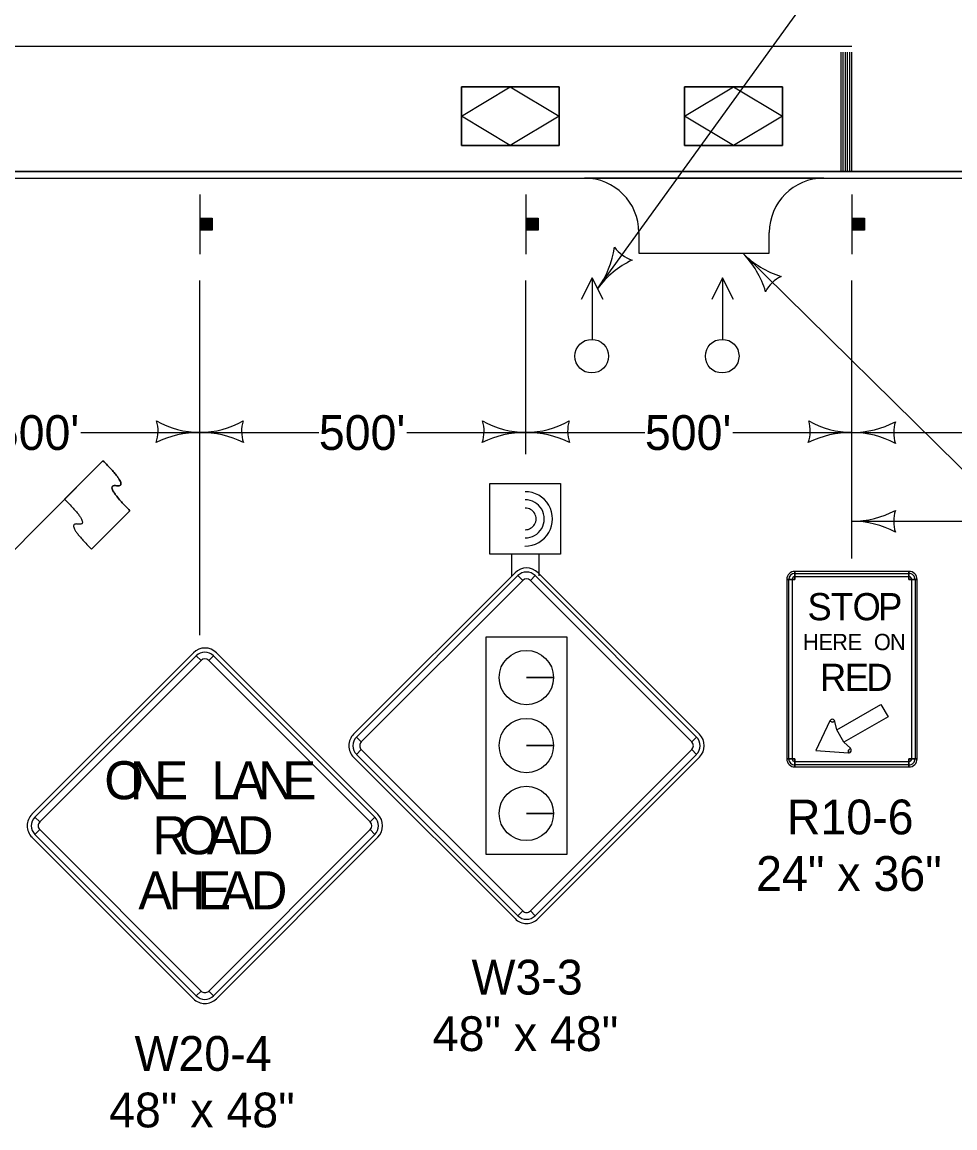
# Model space of a CAD drawing. Extents: x -2134934 to -2122394, y -2139046 to -2137036.
# Drawn here: x -2134616 to -2134187, y -2138105 to -2137596 of the extents above; entities that cross this region are included whole.
import ezdxf

# ---------------------------------------------------------------- set-up
doc = ezdxf.new("R2010")
doc.units = 0
for name, color, linetype in [('Barrier', 7, 'Continuous'), ('BridgeSuperStructureExisting', 7, 'Continuous'), ('DsnShtPlotIdentification', 7, 'Continuous'), ('DsnShtPlotShape', 7, 'Continuous'), ('dsnTextFinalPlan', 7, 'Continuous'), ('TC_Barrier', 7, 'Continuous')]:
    doc.layers.add(name, color=color, linetype=linetype)

msp = doc.modelspace()

# ---------------------------------------------------------------- linework, layer by layer
at = {"layer": 'Barrier'}
for p, q in [((-2134636.31, -2137855.42), (-2134578.99, -2137798.11)), ((-2134578.99, -2137798.11), (-2134596.67, -2137815.79)), ((-2134584.29, -2137838.78), (-2134566.61, -2137821.1)), ((-2134260.69, -2137852.75), (-2134260.69, -2137849)), ((-2134208.19, -2137849), (-2134208.19, -2137852.75)), ((-2134389.44, -2137849.65), (-2134463.68, -2137923.9)), ((-2134388.11, -2137850.98), (-2134385.9, -2137853.19)), ((-2134382.37, -2137853.19), (-2134380.16, -2137850.98)), ((-2134304.59, -2137923.9), (-2134378.83, -2137849.65)), ((-2134264.44, -2137852.75), (-2134260.69, -2137852.75)), ((-2134263.5, -2137852.75), (-2134261.94, -2137852.75)), ((-2134260.69, -2137851.5), (-2134260.69, -2137849.93)), ((-2134208.19, -2137849.93), (-2134208.19, -2137851.5)), ((-2134208.19, -2137852.75), (-2134204.44, -2137852.75)), ((-2134206.94, -2137852.75), (-2134205.38, -2137852.75)), ((-2134537.4, -2137886.48), (-2134611.65, -2137960.72)), ((-2134536.08, -2137887.8), (-2134533.87, -2137890.01)), ((-2134530.33, -2137890.01), (-2134528.12, -2137887.8)), ((-2134452.55, -2137960.72), (-2134526.8, -2137886.48)), ((-2134371.73, -2137897.87), (-2134384.23, -2137897.87)), ((-2134384.23, -2137897.87), (-2134371.73, -2137897.87)), ((-2134244.58, -2137917.73), (-2134243.48, -2137918.31)), ((-2134243.48, -2137918.31), (-2134242.26, -2137918.04)), ((-2134460.15, -2137927.43), (-2134462.36, -2137925.22)), ((-2134305.91, -2137925.22), (-2134308.12, -2137927.43)), ((-2134371.73, -2137929.12), (-2134384.23, -2137929.12)), ((-2134384.23, -2137929.12), (-2134371.73, -2137929.12)), ((-2134235.13, -2137930.38), (-2134235.98, -2137931.3)), ((-2134463.68, -2137934.5), (-2134389.44, -2138008.75)), ((-2134462.36, -2137933.18), (-2134460.15, -2137930.97)), ((-2134378.83, -2138008.75), (-2134304.59, -2137934.5)), ((-2134308.12, -2137930.97), (-2134305.91, -2137933.18)), ((-2134260.69, -2137935.24), (-2134264.44, -2137935.24)), ((-2134261.94, -2137935.24), (-2134263.5, -2137935.24)), ((-2134260.69, -2137938.99), (-2134260.69, -2137935.24)), ((-2134235.98, -2137931.3), (-2134236.03, -2137932.55)), ((-2134204.44, -2137935.24), (-2134208.19, -2137935.24)), ((-2134208.19, -2137935.24), (-2134208.19, -2137938.99)), ((-2134205.38, -2137935.24), (-2134206.94, -2137935.24)), ((-2134260.69, -2137938.06), (-2134260.69, -2137936.49)), ((-2134208.19, -2137936.49), (-2134208.19, -2137938.06)), ((-2134371.73, -2137960.37), (-2134384.23, -2137960.37)), ((-2134384.23, -2137960.37), (-2134371.73, -2137960.37)), ((-2134608.11, -2137964.26), (-2134610.32, -2137962.05)), ((-2134453.88, -2137962.05), (-2134456.08, -2137964.26)), ((-2134611.65, -2137971.33), (-2134537.4, -2138045.58)), ((-2134610.32, -2137970.01), (-2134608.11, -2137967.8)), ((-2134526.8, -2138045.58), (-2134452.55, -2137971.33)), ((-2134456.08, -2137967.8), (-2134453.88, -2137970.01)), ((-2134385.9, -2138005.21), (-2134388.11, -2138007.42)), ((-2134380.16, -2138007.42), (-2134382.37, -2138005.21)), ((-2134533.87, -2138042.04), (-2134536.08, -2138044.25)), ((-2134528.12, -2138044.25), (-2134530.33, -2138042.04))]:
    msp.add_line(p, q, dxfattribs=at)
for points in [[(-2134260.69, -2137938.99), (-2134208.19, -2137938.99), (-2134208.19, -2137935.24), (-2134204.44, -2137935.24), (-2134204.44, -2137852.75), (-2134208.19, -2137852.75), (-2134208.19, -2137849), (-2134260.69, -2137849), (-2134260.69, -2137852.75), (-2134264.44, -2137852.75), (-2134264.44, -2137935.24), (-2134260.69, -2137935.24), (-2134260.69, -2137938.99)], [(-2134388.11, -2137850.98), (-2134462.36, -2137925.22), (-2134460.15, -2137927.43), (-2134385.9, -2137853.19), (-2134388.11, -2137850.98)], [(-2134305.91, -2137925.22), (-2134380.16, -2137850.98), (-2134382.37, -2137853.19), (-2134308.12, -2137927.43), (-2134305.91, -2137925.22)], [(-2134261.94, -2137852.75), (-2134261.94, -2137935.24), (-2134263.5, -2137935.24), (-2134263.5, -2137852.75), (-2134261.94, -2137852.75)], [(-2134208.19, -2137851.5), (-2134260.69, -2137851.5), (-2134260.69, -2137849.93), (-2134208.19, -2137849.93), (-2134208.19, -2137851.5)], [(-2134206.94, -2137935.24), (-2134206.94, -2137852.75), (-2134205.38, -2137852.75), (-2134205.38, -2137935.24), (-2134206.94, -2137935.24)], [(-2134365.4, -2137879.26), (-2134402.87, -2137879.26), (-2134402.87, -2137979.15), (-2134365.4, -2137979.15), (-2134365.4, -2137879.26)], [(-2134536.08, -2137887.8), (-2134610.32, -2137962.05), (-2134608.11, -2137964.26), (-2134533.87, -2137890.01), (-2134536.08, -2137887.8)], [(-2134453.88, -2137962.05), (-2134528.12, -2137887.8), (-2134530.33, -2137890.01), (-2134456.08, -2137964.26), (-2134453.88, -2137962.05)], [(-2134221.07, -2137910.24), (-2134217.79, -2137915.93), (-2134238.1, -2137927.65), (-2134241.38, -2137921.97), (-2134221.07, -2137910.24)], [(-2134251.09, -2137931.37), (-2134236.03, -2137932.55), (-2134235.98, -2137931.3), (-2134235.13, -2137930.38), (-2134238.1, -2137927.65), (-2134241.38, -2137921.97), (-2134242.26, -2137918.04), (-2134243.48, -2137918.31), (-2134244.58, -2137917.73), (-2134251.09, -2137931.37)], [(-2134462.36, -2137933.18), (-2134388.11, -2138007.42), (-2134385.9, -2138005.21), (-2134460.15, -2137930.97), (-2134462.36, -2137933.18)], [(-2134380.16, -2138007.42), (-2134305.91, -2137933.18), (-2134308.12, -2137930.97), (-2134382.37, -2138005.21), (-2134380.16, -2138007.42)], [(-2134260.69, -2137936.49), (-2134208.19, -2137936.49), (-2134208.19, -2137938.06), (-2134260.69, -2137938.06), (-2134260.69, -2137936.49)], [(-2134610.32, -2137970.01), (-2134536.08, -2138044.25), (-2134533.87, -2138042.04), (-2134608.11, -2137967.8), (-2134610.32, -2137970.01)], [(-2134528.12, -2138044.25), (-2134453.88, -2137970.01), (-2134456.08, -2137967.8), (-2134530.33, -2138042.04), (-2134528.12, -2138044.25)]]:
    msp.add_lwpolyline(points, close=True, dxfattribs=at)
for centre in [(-2134384.23, -2137897.87), (-2134384.23, -2137929.12), (-2134384.23, -2137960.37)]:
    msp.add_circle(centre, 12.5, dxfattribs=at)
for centre, radius, start, end in [((-2134384.14, -2137854.96), 7.5, 45, 134.9997), ((-2134384.14, -2137854.96), 5.62, 45, 134.9997), ((-2134260.69, -2137852.75), 3.75, 90.0002, 179.9998), ((-2134208.19, -2137852.75), 3.75, 0, 90.0002), ((-2134384.14, -2137854.96), 2.5, 45, 134.9997), ((-2134260.69, -2137852.75), 2.81, 90.0002, 179.9998), ((-2134260.69, -2137852.75), 1.25, 90.0002, 179.9998), ((-2134208.19, -2137852.75), 2.81, 0, 90.0002), ((-2134208.19, -2137852.75), 1.25, 0, 90.0002), ((-2134532.1, -2137891.78), 7.5, 45, 134.9997), ((-2134532.1, -2137891.78), 5.62, 45, 134.9997), ((-2134532.1, -2137891.78), 2.5, 45, 134.9997), ((-2134243.48, -2137918.31), 1.25, 12.6223, 152.2756), ((-2134458.38, -2137929.2), 7.5, 134.9997, 225), ((-2134458.38, -2137929.2), 5.62, 134.9997, 225), ((-2134309.89, -2137929.2), 5.62, 315.0002, 44.9998), ((-2134309.89, -2137929.2), 7.5, 315.0002, 44.9998), ((-2134458.38, -2137929.2), 2.5, 134.9997, 225), ((-2134309.89, -2137929.2), 2.5, 315.0002, 44.9998), ((-2134235.98, -2137931.3), 1.25, 267.7243, 47.3776), ((-2134260.69, -2137935.24), 3.75, 179.9998, 270.0001), ((-2134260.69, -2137935.24), 2.81, 179.9998, 270.0001), ((-2134260.69, -2137935.24), 1.25, 179.9998, 270.0001), ((-2134208.19, -2137935.24), 3.75, 270.0001, 0.0003), ((-2134208.19, -2137935.24), 2.81, 270.0001, 0.0003), ((-2134208.19, -2137935.24), 1.25, 270.0001, 0.0003), ((-2134606.34, -2137966.03), 7.5, 134.9997, 225), ((-2134457.85, -2137966.03), 7.5, 315.0002, 44.9998), ((-2134606.34, -2137966.03), 5.62, 134.9997, 225), ((-2134606.34, -2137966.03), 2.5, 134.9997, 225), ((-2134457.85, -2137966.03), 2.5, 315.0002, 44.9998), ((-2134457.85, -2137966.03), 5.62, 315.0002, 44.9998), ((-2134384.14, -2138003.45), 2.5, 225, 315.0002), ((-2134384.14, -2138003.45), 7.5, 225, 315.0002), ((-2134384.14, -2138003.45), 5.62, 225, 315.0002), ((-2134532.1, -2138040.27), 2.5, 225, 315.0002), ((-2134532.1, -2138040.27), 7.5, 225, 315.0002), ((-2134532.1, -2138040.27), 5.62, 225, 315.0002)]:
    msp.add_arc(centre, radius, start, end, dxfattribs=at)
for points in [[(-2134566.61, -2137821.1), (-2134578.99, -2137808.72), (-2134566.61, -2137810.49), (-2134578.99, -2137798.11)], [(-2134596.67, -2137815.79), (-2134584.29, -2137828.17), (-2134596.66, -2137826.4), (-2134584.29, -2137838.78)]]:
    msp.add_open_spline(points, degree=2, dxfattribs=at)
at = {"layer": 'BridgeSuperStructureExisting'}
for p, q in [((-2134351.45, -2137718.98), (-2134176.64, -2137477.16)), ((-2134239.44, -2137665.16), (-2134239.44, -2137610.16)), ((-2134238.44, -2137665.16), (-2134238.44, -2137610.16)), ((-2134237.44, -2137665.16), (-2134237.44, -2137610.16)), ((-2134236.44, -2137665.16), (-2134236.44, -2137610.16)), ((-2134235.44, -2137665.16), (-2134235.44, -2137610.16)), ((-2134234.44, -2137665.16), (-2134234.44, -2137610.16)), ((-2134414.12, -2137653.13), (-2134414.12, -2137626.13)), ((-2134414.12, -2137626.13), (-2134369.12, -2137626.13)), ((-2134414.12, -2137653.13), (-2134414.12, -2137626.13)), ((-2134414.12, -2137626.13), (-2134369.12, -2137626.13)), ((-2134369.12, -2137626.13), (-2134414.12, -2137626.13)), ((-2134414.12, -2137626.13), (-2134414.12, -2137653.13)), ((-2134369.12, -2137653.13), (-2134369.12, -2137626.13)), ((-2134369.12, -2137626.13), (-2134369.12, -2137653.13)), ((-2134369.12, -2137653.13), (-2134369.12, -2137626.13)), ((-2134311.44, -2137653.13), (-2134311.44, -2137626.13)), ((-2134311.44, -2137626.13), (-2134266.44, -2137626.13)), ((-2134311.44, -2137653.13), (-2134311.44, -2137626.13)), ((-2134311.44, -2137626.13), (-2134266.44, -2137626.13)), ((-2134266.44, -2137626.13), (-2134311.44, -2137626.13)), ((-2134311.44, -2137626.13), (-2134311.44, -2137653.13)), ((-2134266.44, -2137653.13), (-2134266.44, -2137626.13)), ((-2134266.44, -2137626.13), (-2134266.44, -2137653.13)), ((-2134266.44, -2137653.13), (-2134266.44, -2137626.13)), ((-2134414.12, -2137653.13), (-2134369.12, -2137653.13)), ((-2134369.12, -2137653.13), (-2134414.12, -2137653.13)), ((-2134414.12, -2137653.13), (-2134369.12, -2137653.13)), ((-2134311.44, -2137653.13), (-2134266.44, -2137653.13)), ((-2134266.44, -2137653.13), (-2134311.44, -2137653.13)), ((-2134311.44, -2137653.13), (-2134266.44, -2137653.13)), ((-2134884.44, -2137665.16), (-2133384.44, -2137665.16)), ((-2134247.44, -2137668.16), (-2134357.44, -2137668.16)), ((-2134534.44, -2137675.66), (-2134534.44, -2137703.16)), ((-2134384.44, -2137675.66), (-2134384.44, -2137703.16)), ((-2134234.44, -2137675.66), (-2134234.44, -2137703.16)), ((-2134534.03, -2137692.11), (-2134534.03, -2137686.52)), ((-2134533.75, -2137686.52), (-2134533.75, -2137692.11)), ((-2134533.48, -2137692.11), (-2134533.48, -2137686.52)), ((-2134533.22, -2137686.52), (-2134533.22, -2137692.11)), ((-2134533, -2137692.11), (-2134533, -2137686.52)), ((-2134532.79, -2137686.52), (-2134532.79, -2137692.11)), ((-2134532.45, -2137692.11), (-2134532.45, -2137686.52)), ((-2134532.19, -2137686.52), (-2134532.19, -2137692.11)), ((-2134531.97, -2137692.11), (-2134531.98, -2137686.52)), ((-2134531.65, -2137686.52), (-2134531.65, -2137692.11)), ((-2134531.27, -2137692.11), (-2134531.27, -2137686.52)), ((-2134530.84, -2137686.52), (-2134530.84, -2137692.11)), ((-2134530.62, -2137692.11), (-2134530.63, -2137686.52)), ((-2134530.2, -2137686.52), (-2134530.18, -2137692.11)), ((-2134529.98, -2137692.11), (-2134529.98, -2137686.52)), ((-2134529.66, -2137686.52), (-2134529.66, -2137692.11)), ((-2134529.43, -2137692.11), (-2134529.43, -2137686.52)), ((-2134529.12, -2137686.52), (-2134529.12, -2137692.11)), ((-2134384.03, -2137692.11), (-2134384.03, -2137686.52)), ((-2134383.75, -2137686.52), (-2134383.75, -2137692.11)), ((-2134383.48, -2137692.11), (-2134383.48, -2137686.52)), ((-2134383.22, -2137686.52), (-2134383.22, -2137692.11)), ((-2134383, -2137692.11), (-2134383, -2137686.52)), ((-2134382.79, -2137686.52), (-2134382.79, -2137692.11)), ((-2134382.45, -2137692.11), (-2134382.45, -2137686.52)), ((-2134382.19, -2137686.52), (-2134382.19, -2137692.11)), ((-2134381.97, -2137692.11), (-2134381.98, -2137686.52)), ((-2134381.65, -2137686.52), (-2134381.65, -2137692.11)), ((-2134381.27, -2137692.11), (-2134381.27, -2137686.52)), ((-2134380.84, -2137686.52), (-2134380.84, -2137692.11)), ((-2134380.62, -2137692.11), (-2134380.63, -2137686.52)), ((-2134380.2, -2137686.52), (-2134380.18, -2137692.11)), ((-2134379.98, -2137692.11), (-2134379.98, -2137686.52)), ((-2134379.66, -2137686.52), (-2134379.66, -2137692.11)), ((-2134379.43, -2137692.11), (-2134379.43, -2137686.52)), ((-2134379.12, -2137686.52), (-2134379.12, -2137692.11)), ((-2134234.03, -2137692.11), (-2134234.03, -2137686.52)), ((-2134233.75, -2137686.52), (-2134233.75, -2137692.11)), ((-2134233.49, -2137692.11), (-2134233.49, -2137686.52)), ((-2134233.22, -2137686.52), (-2134233.22, -2137692.11)), ((-2134233, -2137692.11), (-2134233, -2137686.52)), ((-2134232.79, -2137686.52), (-2134232.79, -2137692.11)), ((-2134232.45, -2137692.11), (-2134232.45, -2137686.52)), ((-2134232.19, -2137686.52), (-2134232.19, -2137692.11)), ((-2134231.97, -2137692.11), (-2134231.99, -2137686.52)), ((-2134231.65, -2137686.52), (-2134231.65, -2137692.11)), ((-2134231.27, -2137692.11), (-2134231.27, -2137686.52)), ((-2134230.84, -2137686.52), (-2134230.84, -2137692.11)), ((-2134230.62, -2137692.11), (-2134230.64, -2137686.52)), ((-2134230.2, -2137686.52), (-2134230.19, -2137692.11)), ((-2134229.98, -2137692.11), (-2134229.98, -2137686.52)), ((-2134229.66, -2137686.52), (-2134229.66, -2137692.11)), ((-2134229.44, -2137692.11), (-2134229.44, -2137686.52)), ((-2134229.12, -2137686.52), (-2134229.12, -2137692.11)), ((-2134096.53, -2137887.94), (-2134284.66, -2137702.65)), ((-2134534.44, -2137878.33), (-2134534.44, -2137715.16)), ((-2134384.44, -2137795.16), (-2134384.44, -2137715.16)), ((-2134353.76, -2137742.3), (-2134353.76, -2137714.35)), ((-2134293.76, -2137742.3), (-2134293.76, -2137714.35)), ((-2134234.44, -2137843.11), (-2134234.44, -2137715.16)), ((-2134589.19, -2137785.16), (-2134534.44, -2137785.16)), ((-2134534.44, -2137785.16), (-2134479.69, -2137785.16)), ((-2134439.19, -2137785.16), (-2134384.44, -2137785.16)), ((-2134384.44, -2137785.16), (-2134329.69, -2137785.16)), ((-2134289.19, -2137785.16), (-2134234.44, -2137785.16)), ((-2134234.44, -2137785.16), (-2134152.68, -2137785.16)), ((-2134234.44, -2137825.98), (-2133930.88, -2137825.98)), ((-2134390.98, -2137841.1), (-2134390.98, -2137851.1)), ((-2134378.48, -2137841.1), (-2134378.48, -2137851.1))]:
    msp.add_line(p, q, dxfattribs=at)
for points in [[(-2134534.35, -2137692.11), (-2134534.35, -2137686.48), (-2134528.72, -2137686.48), (-2134528.72, -2137692.11)], [(-2134384.35, -2137692.11), (-2134384.35, -2137686.48), (-2134378.72, -2137686.48), (-2134378.72, -2137692.11)], [(-2134234.35, -2137692.11), (-2134234.35, -2137686.48), (-2134228.72, -2137686.48), (-2134228.72, -2137692.11)], [(-2134400.98, -2137841.1), (-2134400.98, -2137808.6), (-2134368.48, -2137808.6), (-2134368.48, -2137841.1)]]:
    msp.add_lwpolyline(points, close=True, dxfattribs=at)
for points in [[(-2134332.44, -2137693.16), (-2134332.44, -2137702.65), (-2134272.44, -2137702.65), (-2134272.44, -2137693.16)], [(-2134348.95, -2137723.98), (-2134353.95, -2137713.98), (-2134358.95, -2137723.98)], [(-2134288.95, -2137723.98), (-2134293.95, -2137713.98), (-2134298.95, -2137723.98)]]:
    msp.add_lwpolyline(points, dxfattribs=at)
for centre in [(-2134354.13, -2137750.03), (-2134294.13, -2137750.03)]:
    msp.add_circle(centre, 7.74, dxfattribs=at)
for centre, radius, start, end in [((-2134357.44, -2137693.16), 25, 0, 90), ((-2134247.44, -2137693.16), 25, 90, 180), ((-2134570.06, -2137784.54), 16.42, 341.2666, 16.7334), ((-2134533.69, -2137742.67), 42.5, 240.9275, 268.9824), ((-2134535.2, -2137742.67), 42.5, 271.0176, 299.0725), ((-2134498.82, -2137784.54), 16.42, 163.2666, 198.7334), ((-2134420.06, -2137784.54), 16.42, 341.2666, 16.7334), ((-2134383.69, -2137742.67), 42.5, 240.9275, 268.9824), ((-2134385.2, -2137742.67), 42.5, 271.0176, 299.0725), ((-2134348.82, -2137784.54), 16.42, 163.2666, 198.7334), ((-2134270.06, -2137784.54), 16.42, 341.2666, 16.7334), ((-2134233.69, -2137742.67), 42.5, 240.9275, 268.9824), ((-2134234.44, -2137742.66), 42.5, 270, 298.0725), ((-2134198.81, -2137785.16), 16.42, 162.2666, 197.7334), ((-2134535.17, -2137827.65), 42.5, 89.0176, 117.0725), ((-2134533.71, -2137827.65), 42.5, 62.9275, 90.9824), ((-2134385.17, -2137827.65), 42.5, 89.0176, 117.0725), ((-2134383.71, -2137827.65), 42.5, 62.9275, 90.9824), ((-2134235.17, -2137827.65), 42.5, 89.0176, 117.0725), ((-2134234.44, -2137827.66), 42.5, 61.9275, 90), ((-2134384.72, -2137824.87), 12.5, 269.4041, 90.5445), ((-2134384.72, -2137824.87), 12.5, 269.4041, 90.5445), ((-2134384.72, -2137824.87), 8.75, 269.4041, 90.5445), ((-2134384.72, -2137824.87), 5, 269.4041, 90.5445)]:
    msp.add_arc(centre, radius, start, end, dxfattribs=at)
at = {"layer": 'DsnShtPlotIdentification'}
for p, q in [((-2134234.44, -2137607.66), (-2134886.94, -2137607.66)), ((-2134884.44, -2137665.16), (-2133384.44, -2137665.16)), ((-2134884.44, -2137665.16), (-2133384.44, -2137665.16)), ((-2134239.44, -2137665.16), (-2134884.44, -2137665.16)), ((-2134238.44, -2137665.16), (-2134239.44, -2137665.16)), ((-2134237.44, -2137665.16), (-2134238.44, -2137665.16)), ((-2134236.44, -2137665.16), (-2134237.44, -2137665.16)), ((-2133384.44, -2137665.16), (-2134234.44, -2137665.16)), ((-2134884.44, -2137668.16), (-2133384.44, -2137668.16)), ((-2134884.44, -2137668.16), (-2133384.44, -2137668.16))]:
    msp.add_line(p, q, dxfattribs=at)
msp.add_lwpolyline([(-2134234.44, -2137665.16), (-2134235.44, -2137665.16), (-2134236.44, -2137665.16)], dxfattribs=at)
at = {"layer": 'DsnShtPlotShape'}
for centre, radius, start, end in [((-2134385.7, -2137693.82), 42.5, 323.701, 351.7735), ((-2134330.35, -2137690.26), 16.42, 215.9676, 251.4343), ((-2134317.2, -2137744.14), 42.5, 115.6285, 143.701), ((-2134314.86, -2137732.56), 42.5, 16.6579, 44.7304), ((-2134254.47, -2137672.74), 42.5, 224.7304, 252.8028), ((-2134259.59, -2137727.96), 16.42, 116.997, 152.4637), ((-2134234.44, -2137783.48), 42.5, 270, 298.0725), ((-2134198.81, -2137825.98), 16.42, 162.2666, 197.7334), ((-2134234.44, -2137868.48), 42.5, 61.9275, 90)]:
    msp.add_arc(centre, radius, start, end, dxfattribs=at)
at = {"layer": 'dsnTextFinalPlan'}
for points in [[(-2134414.12, -2137639.63), (-2134391.62, -2137626.13), (-2134369.12, -2137639.63), (-2134391.62, -2137653.13)], [(-2134311.44, -2137639.63), (-2134288.94, -2137626.13), (-2134266.44, -2137639.63), (-2134288.94, -2137653.13)]]:
    msp.add_lwpolyline(points, close=True, dxfattribs=at)
at = {"layer": 'TC_Barrier'}
msp.add_line((-2134566.61, -2137821.1), (-2134584.29, -2137838.78), dxfattribs=at)
for points in [[(-2134578.99, -2137798.11), (-2134566.61, -2137810.49), (-2134578.99, -2137808.72), (-2134566.61, -2137821.1)], [(-2134596.67, -2137815.79), (-2134584.29, -2137828.17), (-2134596.66, -2137826.4), (-2134584.29, -2137838.78)]]:
    msp.add_open_spline(points, degree=2, dxfattribs=at)

# ---------------------------------------------------------------- texts
at = {"layer": 'Barrier'}
for s, height, p in [('S', 12.5, (-2134254.89, -2137871.5)), ('T', 12.5, (-2134244.13, -2137871.5)), ('O', 12.5, (-2134234.14, -2137871.5)), ('P', 12.5, (-2134222.39, -2137871.5)), ('H', 7.5, (-2134256.97, -2137885.25)), ('E', 7.5, (-2134249.82, -2137885.25)), ('R', 7.5, (-2134243.56, -2137885.25)), ('E', 7.5, (-2134236.41, -2137885.25)), ('O', 7.5, (-2134224.34, -2137885.25)), ('N', 7.5, (-2134216.96, -2137885.25)), ('R', 12.5, (-2134249.13, -2137904)), ('E', 12.5, (-2134237.8, -2137904)), ('D', 12.5, (-2134227.84, -2137904)), ('O', 17.5, (-2134578.38, -2137953.84)), ('N', 17.5, (-2134566.61, -2137953.84)), ('E', 17.5, (-2134555.38, -2137953.84)), ('L', 17.5, (-2134529.13, -2137953.84)), ('A', 17.5, (-2134519.93, -2137953.84)), ('N', 17.5, (-2134507.67, -2137953.84)), ('E', 17.5, (-2134496.44, -2137953.84)), ('R10-6', 16, (-2134264.37, -2137969.99)), ('R', 17.5, (-2134556.28, -2137979.15)), ('O', 17.5, (-2134543.99, -2137979.15)), ('A', 17.5, (-2134531.15, -2137979.15)), ('D', 17.5, (-2134517.49, -2137979.15)), ('24" x 36"', 16, (-2134278.51, -2137995.99)), ('A', 17.5, (-2134562.71, -2138004.47)), ('H', 17.5, (-2134548.85, -2138004.47)), ('E', 17.5, (-2134535.63, -2138004.47)), ('A', 17.5, (-2134524.92, -2138004.47)), ('D', 17.5, (-2134511.05, -2138004.47)), ('W3-3', 16, (-2134409.43, -2138043.67)), ('48" x 48"', 16, (-2134427.31, -2138069.67)), ('W20-4', 16, (-2134564.47, -2138078.77)), ('48" x 48"', 16, (-2134576.17, -2138104.77))]:
    msp.add_text(s, height=height, dxfattribs=at).set_placement(p)
at = {"layer": 'BridgeSuperStructureExisting'}
for p in [(-2134629.69, -2137793.16), (-2134479.69, -2137793.16), (-2134329.69, -2137793.16)]:
    msp.add_text("500'", height=16, dxfattribs=at).set_placement(p)

doc.saveas('drawing.dxf')
